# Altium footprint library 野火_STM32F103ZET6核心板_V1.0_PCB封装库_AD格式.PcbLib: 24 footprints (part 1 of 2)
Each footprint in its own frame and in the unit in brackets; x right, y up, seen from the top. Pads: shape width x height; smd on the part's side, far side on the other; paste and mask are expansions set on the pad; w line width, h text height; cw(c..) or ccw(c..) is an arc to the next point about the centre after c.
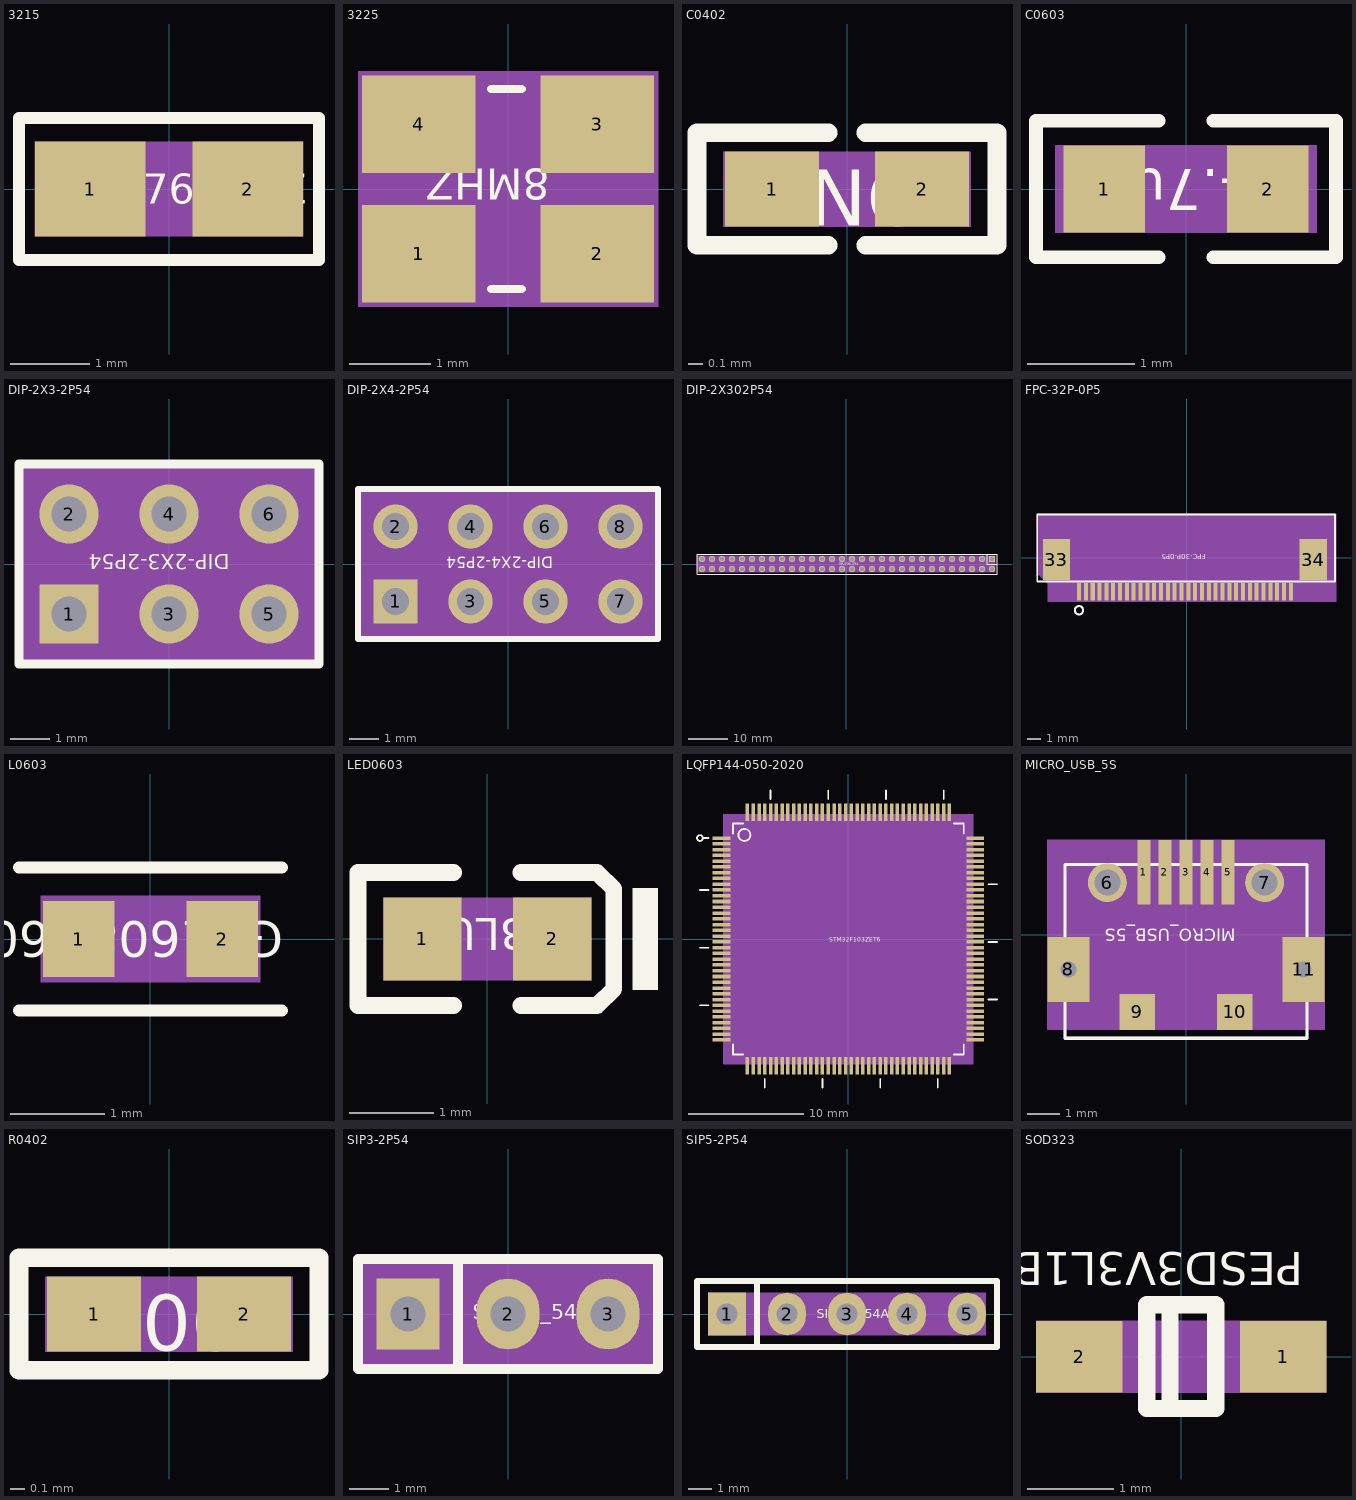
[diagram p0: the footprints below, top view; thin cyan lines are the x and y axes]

## 3215 [mm] "3215"
pads (2):
  rect 1.4x1.2 smd: 1(-1,0) 2(1,0)
Top Overlay:
  lines w0.15: -1.9,-0.9 1.9,-0.9 1.9,0.9 -1.9,0.9 -1.9,-0.9
  text "32.768KHZ" at -1.153,-0.184 h0.38
Mechanical 9:
  text "1" at -1,0.152 h0.38
  text "2" at 1,0.152 h0.38
Mechanical 11:
  region: -1.7,-0.6 1.7,-0.6 1.7,0.6 -1.7,0.6

## 3225 [mil] "3225"
pads (4):
  rect 55.12x47.24 smd: 1(-43.31,-31.49) 2(43.3,-31.49) 3(43.3,31.5) 4(-43.31,31.5)
Top Overlay:
  lines w3.94: -8.31,-48.5 6.69,-48.5 ; -8.31,48.52 6.69,48.52
  text "8MHZ" at 20.15,9.75 h15
Mechanical 9:
  text "1" at -43.31,-37.49 h15
  text "3" at 43.3,25.5 h15
  text "4" at -43.31,25.5 h15
  text "2" at 43.3,-37.49 h15
Mechanical 11:
  region: -72.84,-57.08 72.83,-57.08 72.83,57.09 -72.84,57.09

## C0402 [mil] "C0402"
pads (2):
  rect 25x20 smd: 1(-20,0) 2(20,0)
Top Overlay:
  lines w5: -5,-15 -40,-15 -40,15 -5,15 ; 5,-15 40,-15 40,15 5,15
  text "NC" at -10.05,-9.75 h15
Mechanical 9:
  text "1" at -30,0 h25
  text "2" at 10,0 h25
Mechanical 11:
  region: -33,10 33,10 33,-10 -33,-10

## C0603 [mil] "C0603"
pads (2):
  rect 30x32 smd: 1(-30,0) 2(30,0)
Top Overlay:
  lines w5: -10,-25 -55,-25 -55,25 -10,25 ; 10,-25 55,-25 55,25 10,25
  text "4.7uF" at 25.2,7.25 h15
Mechanical 9:
  text "1" at -20,0 h25
  text "2" at 40,0 h25
Mechanical 11:
  region: -48,16 48,16 48,-16 -48,-16
Mechanical 12:
  text "C0603" at -117,37 h50

## DIP-2X3-2P54 [mil] "DIP-2X3-2P54"
pads (6):
  rect 59.06x59.06 / inner round 60 / far side rect 59.06x59.06 hole 35.43: 1(-100,-50)
  round 59.06 / inner round 60 / far side round 59.06 hole 35.43: 2(-100,50) 3(0,-50) 4(0,50) 5(100,-50) 6(100,50)
Top Overlay:
  lines w8.66: -139.37,100 -150,100 ; -150,100 -150,-100 150,-100 150,100 -150,100
  text "DIP-2X3-2P54" at 60.55,9.75 h15
Mechanical 9:
  text "4" at 0,40 h25
  text "3" at 0,-60 h25
  text "1" at -100,-60 h25
  text "2" at -100,40 h25
  text "5" at 100,-60 h25
  text "6" at 100,40 h25
Mechanical 11:
  region: -150,-100 150,-100 150,100 -150,100
Mechanical 12:
  text ".Designator" at -145,97 h35

## DIP-2X4-2P54 [mil] "DIP-2X4-2P54"
pads (8):
  rect 59.06x59.06 / inner round 60 / far side rect 59.06x59.06 hole 35.43: 1(-150,-50)
  round 59.06 / inner round 60 / far side round 59.06 hole 35.43: 2(-150,50) 3(-50,-50) 4(-50,50) 5(50,-50) 6(50,50) 7(150,-50) 8(150,50)
Top Overlay:
  lines w8.66: -189.37,100 -200,100 ; -200,100 -200,-100 200,-100 200,100 -200,100
  text "DIP-2X4-2P54" at 60.55,9.75 h15
Mechanical 9:
  text "3" at -50,-60 h25
  text "4" at -50,40 h25
  text "5" at 50,-60 h25
  text "6" at 50,40 h25
  text "2" at -150,40 h25
  text "1" at -150,-60 h25
  text "7" at 150,-60 h25
  text "8" at 150,40 h25
Mechanical 11:
  region: -200,-100 200,-100 200,100 -200,100
Mechanical 12:
  text ".Designator" at -195,97 h35

## DIP-2X302P54 [mil] "DIP-2X302P54"
pads (60):
  rect 62.99x62.99 / inner round 60 / far side rect 62.99x62.99 hole 35.43: 1(1459.5,50)
  round 62.99 / inner round 60 / far side round 62.99 hole 35.43: 2(1459.5,-50) 3(1359.5,50) 4(1359.5,-50) 5(1259.5,50) 6(1259.5,-50) 7(1159.5,50) 8(1159.5,-50) 9(1059.5,50) 10(1059.5,-50) 11(959.5,50) 12(959.5,-50) 13(859.5,50) 14(859.5,-50) 15(759.5,50) 16(759.5,-50) 17(659.5,50) 18(659.5,-50) 19(559.5,50) 20(559.5,-50) 21(459.5,50) 22(459.5,-50) 23(359.5,50) 24(359.5,-50) 25(259.5,50) 26(259.5,-50) 27(159.5,50) 28(159.5,-50) 29(59.5,50) 30(59.5,-50) 31(-40.5,50) 32(-40.5,-50) 33(-140.5,50) 34(-140.5,-50) 35(-240.5,50) 36(-240.5,-50) 37(-340.5,50) 38(-340.5,-50) 39(-440.5,50) 40(-440.5,-50) 41(-540.5,50) 42(-540.5,-50) 43(-640.5,50) 44(-640.5,-50) 45(-740.5,50) 46(-740.5,-50) 47(-840.5,50) 48(-840.5,-50) 49(-940.5,50) 50(-940.5,-50) 51(-1040.5,50) 52(-1040.5,-50) 53(-1140.5,50) 54(-1140.5,-50) 55(-1240.5,50) 56(-1240.5,-50) 57(-1340.5,50) 58(-1340.5,-50) 59(-1440.5,50) 60(-1440.5,-50)
Top Overlay:
  lines w12: 1409.5,100 1409.5,0 1509.5,0 ; -1490.5,-100 1509.5,-100 1509.5,100 -1490.5,100 -1490.5,-100
  text "DIP_2X30_2P54" at -65.6,-7.25 h15
Mechanical 9:
  text "60" at -1420.5,-50 h25
  text "7" at 1169.5,50 h25
  text "11" at 979.5,50 h25
  text "33" at -120.5,50 h25
  text "35" at -220.5,50 h25
  text "12" at 979.5,-50 h25
  text "51" at -1020.5,50 h25
  text "45" at -720.5,50 h25
  text "48" at -820.5,-50 h25
  text "40" at -420.5,-50 h25
  text "47" at -820.5,50 h25
  text "36" at -220.5,-50 h25
  text "34" at -120.5,-50 h25
  text "50" at -920.5,-50 h25
  text "49" at -920.5,50 h25
  text "16" at 779.5,-50 h25
  text "21" at 479.5,50 h25
  text "25" at 279.5,50 h25
  text "14" at 879.5,-50 h25
  text "39" at -420.5,50 h25
  text "44" at -620.5,-50 h25
  text "43" at -620.5,50 h25
  text "52" at -1020.5,-50 h25
  text "18" at 679.5,-50 h25
  text "42" at -520.5,-50 h25
  text "41" at -520.5,50 h25
  text "20" at 579.5,-50 h25
  text "56" at -1220.5,-50 h25
  text "55" at -1220.5,50 h25
  text "53" at -1120.5,50 h25
  text "30" at 79.5,-50 h25
  text "27" at 179.5,50 h25
  text "17" at 679.5,50 h25
  text "23" at 379.5,50 h25
  text "15" at 779.5,50 h25
  text "31" at -20.5,50 h25
  text "58" at -1320.5,-50 h25
  text "54" at -1120.5,-50 h25
  text "57" at -1320.5,50 h25
  text "32" at -20.5,-50 h25
  text "29" at 79.5,50 h25
  text "24" at 379.5,-50 h25
  text "22" at 479.5,-50 h25
  text "5" at 1269.5,50 h25
  text "4" at 1369.5,-50 h25
  text "10" at 1079.5,-50 h25
  text "9" at 1069.5,50 h25
  text "8" at 1169.5,-50 h25
  text "13" at 879.5,50 h25
  text "28" at 179.5,-50 h25
  text "26" at 279.5,-50 h25
  text "19" at 579.5,50 h25
  text "1" at 1469.5,50 h25
  text "2" at 1469.5,-50 h25
  text "3" at 1369.5,50 h25
  text "38" at -320.5,-50 h25
  text "37" at -320.5,50 h25
  text "59" at -1420.5,50 h25
  text "6" at 1269.5,-50 h25
  text "46" at -720.5,-50 h25
Mechanical 10:
  region: 1490.5,-81 1490.5,81 -1490.5,81 -1490.5,-81
Mechanical 14:
  text ".Designator" at 1507.5,-115 h35

## FPC-32P-0P5 [mm] "FPC-32P-0P5"
pads (34):
  rect 0.3x1.3 smd: 1(-7.865,-2.483) 2(-7.365,-2.483) 3(-6.865,-2.483) 4(-6.365,-2.483) 5(-5.865,-2.483) 6(-5.365,-2.483) 7(-4.865,-2.483) 8(-4.365,-2.483) 9(-3.865,-2.483) 10(-3.365,-2.483) 11(-2.865,-2.483) 12(-2.365,-2.483) 13(-1.865,-2.483) 14(-1.365,-2.483) 15(-0.865,-2.483) 16(-0.365,-2.483) 17(0.135,-2.483) 18(0.635,-2.483) 19(1.135,-2.483) 20(1.635,-2.483) 21(2.135,-2.483) 22(2.635,-2.483) 23(3.135,-2.483) 24(3.635,-2.483) 25(4.135,-2.483) 26(4.635,-2.483) 27(5.135,-2.483) 28(5.635,-2.483) 29(6.135,-2.483) 30(6.635,-2.483) 31(7.135,-2.483) 32(7.635,-2.483)
  rect 2x3 smd: 33(-9.515,-0.133) 34(9.285,-0.133)
Top Overlay:
  circle w0.152: c-7.865,-3.845 r0.305
  lines w0.127: -10.915,-1.733 10.872,-1.733 10.872,3.167 -10.915,3.167 -10.915,-1.733
  text "FPC-30P-0P5" at 1.41,0.248 h0.38
Mechanical 9:
  text "23" at 3.135,-2.991 h0.64
  text "28" at 5.635,-2.991 h0.64
  text "22" at 2.635,-2.991 h0.64
  text "2" at -7.365,-2.737 h0.64
  text "27" at 5.135,-2.991 h0.64
  text "26" at 4.635,-2.991 h0.64
  text "24" at 3.635,-2.991 h0.64
  text "12" at -2.365,-2.991 h0.64
  text "13" at -1.865,-2.991 h0.64
  text "14" at -1.365,-2.991 h0.64
  text "21" at 2.135,-2.991 h0.64
  text "6" at -5.365,-2.737 h0.64
  text "7" at -4.865,-2.737 h0.64
  text "8" at -4.365,-2.737 h0.64
  text "9" at -3.865,-2.737 h0.64
  text "10" at -3.365,-2.991 h0.64
  text "11" at -2.865,-2.991 h0.64
  text "4" at -6.365,-2.737 h0.64
  text "5" at -5.865,-2.737 h0.64
  text "20" at 1.635,-2.991 h0.64
  text "19" at 1.135,-2.991 h0.64
  text "17" at 0.135,-2.991 h0.64
  text "18" at 0.635,-2.991 h0.64
  text "3" at -6.865,-2.737 h0.64
  text "15" at -0.865,-2.991 h0.64
  text "16" at -0.365,-2.991 h0.64
  text "31" at 7.64,-3.499 h0.64
  text "29" at 6.135,-2.991 h0.64
  text "33" at -9.515,-0.641 h0.64
  text "32" at 8.402,-3.499 h0.64
  text "30" at 6.635,-2.991 h0.64
  text "34" at 9.285,-0.641 h0.64
  text "1" at -7.865,-2.737 h0.64
  text "25" at 4.135,-2.991 h0.64
Mechanical 11:
  region: -10.155,-3.233 10.942,-3.233 10.942,3.232 -10.942,3.232 -10.942,-1.27 -10.79,-1.27 -10.155,-1.905

## L0603 [mil] "L0603"
pads (2):
  rect 30x32 smd: 1(-30,0) 2(30,0)
Top Overlay:
  lines w5: -55,-30 55,-30 ; -55,30 55,30
  text "GZ1608D601TF" at 55.55,7.5 h15
Mechanical 9:
  text "1" at -30,-10 h25
  text "2" at 30,-10 h25
Mechanical 11:
  region: -46,18 46,18 46,-18 -46,-18
Mechanical 12:
  text "L0603" at -115,40 h50
Multi-Layer:
  region: -49,-20 49,-20 49,20 -49,20

## LED0603 [mil] "LED0603"
pads (2):
  rect 36.61x38.58 smd: 1(-30.31,0) 2(30.32,0)
Top Overlay:
  pour cut-out: 67.91,-23.62 79.73,-23.62 79.73,23.62 67.91,23.62
  lines w7.87: -15.75,-31.1 -60.43,-31.1 -60.43,31.1 -15.75,31.1 ; 15.75,-31.1 51.18,-31.1 59.06,-23.5 59.06,23.5 51.18,31.1 15.75,31.1
  text "BLUE" at 20.15,9.75 h15
Mechanical 9:
  text "2" at 40.32,0 h25
  text "1" at -20.31,0 h25
Mechanical 11:
  region: -48.62,-19.29 48.62,-19.29 48.62,19.29 -48.62,19.29

## LQFP144-050-2020 [mil] "LQFP144-050-2020"
pads (144):
  rect 60x12 smd: 1(-433.07,344.49) 2(-433.07,324.8) 3(-433.07,305.12) 4(-433.07,285.43) 5(-433.07,265.75) 6(-433.07,246.06) 7(-433.07,226.38) 8(-433.07,206.69) 9(-433.07,187.01) 10(-433.07,167.32) 11(-433.07,147.64) 12(-433.07,127.95) 13(-433.07,108.27) 14(-433.07,88.58) 15(-433.07,68.9) 16(-433.07,49.21) 17(-433.07,29.53) 18(-433.07,9.84) 19(-433.07,-9.84) 20(-433.07,-29.53) 21(-433.07,-49.21) 22(-433.07,-68.9) 23(-433.07,-88.58) 24(-433.07,-108.27) 25(-433.07,-127.95) 26(-433.07,-147.64) 27(-433.07,-167.32) 28(-433.07,-187.01) 29(-433.07,-206.69) 30(-433.07,-226.38) 31(-433.07,-246.06) 32(-433.07,-265.75) 33(-433.07,-285.43) 34(-433.07,-305.12) 35(-433.07,-324.8) 36(-433.07,-344.49) 73(433.07,-344.49) 74(433.07,-324.8) 75(433.07,-305.12) 76(433.07,-285.43) 77(433.07,-265.75) 78(433.07,-246.06) 79(433.07,-226.38) 80(433.07,-206.69) 81(433.07,-187.01) 82(433.07,-167.32) 83(433.07,-147.64) 84(433.07,-127.95) 85(433.07,-108.27) 86(433.07,-88.58) 87(433.07,-68.9) 88(433.07,-49.21) 89(433.07,-29.53) 90(433.07,-9.84) 91(433.07,9.84) 92(433.07,29.53) 93(433.07,49.21) 94(433.07,68.9) 95(433.07,88.58) 96(433.07,108.27) 97(433.07,127.95) 98(433.07,147.64) 99(433.07,167.32) 100(433.07,187.01) 101(433.07,206.69) 102(433.07,226.38) 103(433.07,246.06) 104(433.07,265.75) 105(433.07,285.43) 106(433.07,305.12) 107(433.07,324.8) 108(433.07,344.49)
  rect 12x60 smd: 37(-344.49,-433.07) 38(-324.8,-433.07) 39(-305.12,-433.07) 40(-285.43,-433.07) 41(-265.75,-433.07) 42(-246.06,-433.07) 43(-226.38,-433.07) 44(-206.69,-433.07) 45(-187.01,-433.07) 46(-167.32,-433.07) 47(-147.64,-433.07) 48(-127.95,-433.07) 49(-108.27,-433.07) 50(-88.58,-433.07) 51(-68.9,-433.07) 52(-49.21,-433.07) 53(-29.53,-433.07) 54(-9.84,-433.07) 55(9.84,-433.07) 56(29.53,-433.07) 57(49.21,-433.07) 58(68.9,-433.07) 59(88.58,-433.07) 60(108.27,-433.07) 61(127.95,-433.07) 62(147.64,-433.07) 63(167.32,-433.07) 64(187.01,-433.07) 65(206.69,-433.07) 66(226.38,-433.07) 67(246.06,-433.07) 68(265.75,-433.07) 69(285.43,-433.07) 70(305.12,-433.07) 71(324.8,-433.07) 72(344.49,-433.07) 109(344.49,433.07) 110(324.8,433.07) 111(305.12,433.07) 112(285.43,433.07) 113(265.75,433.07) 114(246.06,433.07) 115(226.38,433.07) 116(206.69,433.07) 117(187.01,433.07) 118(167.32,433.07) 119(147.64,433.07) 120(127.95,433.07) 121(108.27,433.07) 122(88.58,433.07) 123(68.9,433.07) 124(49.21,433.07) 125(29.53,433.07) 126(9.84,433.07) 127(-9.84,433.07) 128(-29.53,433.07) 129(-49.21,433.07) 130(-68.9,433.07) 131(-88.58,433.07) 132(-108.27,433.07) 133(-127.95,433.07) 134(-147.64,433.07) 135(-167.32,433.07) 136(-187.01,433.07) 137(-206.69,433.07) 138(-226.38,433.07) 139(-246.06,433.07) 140(-265.75,433.07) 141(-285.43,433.07) 142(-305.12,433.07) 143(-324.8,433.07) 144(-344.49,433.07)
Top Overlay:
  circle w6: c-355,355 r20.62
  circle w6: c-506.89,344.49 r9.84
  lines w6: -506.89,-226.38 -477.36,-226.38 ; -506.89,-29.53 -477.36,-29.53 ; -506.89,167.32 -477.36,167.32 ; -497.05,344.49 -477.36,344.49 ; -393.7,-360 -393.7,-393.7 -360,-393.7 ; -393.7,360 -393.7,393.7 -360,393.7 ; -285.43,-506.89 -285.43,-477.36 ; -265.75,477.36 -265.75,506.89 ; -88.58,-506.89 -88.58,-477.36 ; -68.9,477.36 -68.9,506.89 ; 108.27,-506.89 108.27,-477.36 ; 127.95,477.36 127.95,506.89 ; 305.12,-506.89 305.12,-477.36 ; 324.8,477.36 324.8,506.89 ; 360,-393.7 393.7,-393.7 393.7,-360 ; 360,393.7 393.7,393.7 393.7,360 ; 477.36,-206.69 506.89,-206.69 ; 477.36,-9.84 506.89,-9.84 ; 477.36,187.01 506.89,187.01
  text ".Designator" at 26.5,505 h30
  text "STM32F103ZET6" at -65.6,-9.75 h15
Mechanical 9:
  text "71" at 308.8,-433.07 h20
  text "143" at -348.8,433.07 h20
  text "23" at -449.07,-88.58 h20
  text "24" at -449.07,-108.27 h20
  text "8" at -441.07,206.69 h20
  text "9" at -441.07,187.01 h20
  text "106" at 409.07,305.12 h20
  text "6" at -441.07,246.06 h20
  text "124" at 25.21,433.07 h20
  text "93" at 417.07,49.21 h20
  text "92" at 417.07,29.53 h20
  text "91" at 417.07,9.84 h20
  text "90" at 417.07,-9.84 h20
  text "89" at 417.07,-29.53 h20
  text "88" at 417.07,-49.21 h20
  text "87" at 417.07,-68.9 h20
  text "132" at -132.27,433.07 h20
  text "129" at -73.21,433.07 h20
  text "128" at -53.53,433.07 h20
  text "127" at -33.84,433.07 h20
  text "126" at -14.16,433.07 h20
  text "125" at 5.53,433.07 h20
  text "57" at 33.21,-433.07 h20
  text "56" at 13.53,-433.07 h20
  text "21" at -449.07,-49.21 h20
  text "20" at -449.07,-29.53 h20
  text "19" at -449.07,-9.84 h20
  text "18" at -449.07,9.84 h20
  text "15" at -449.07,68.9 h20
  text "14" at -449.07,88.58 h20
  text "13" at -449.07,108.27 h20
  text "12" at -449.07,127.95 h20
  text "55" at -6.16,-433.07 h20
  text "54" at -25.84,-433.07 h20
  text "53" at -45.53,-433.07 h20
  text "50" at -104.58,-433.07 h20
  text "49" at -124.27,-433.07 h20
  text "22" at -449.07,-68.9 h20
  text "11" at -449.07,147.64 h20
  text "10" at -449.07,167.32 h20
  text "60" at 92.27,-433.07 h20
  text "59" at 72.58,-433.07 h20
  text "58" at 52.9,-433.07 h20
  text "5" at -441.07,265.75 h20
  text "4" at -441.07,285.43 h20
  text "3" at -441.07,305.12 h20
  text "2" at -441.07,324.8 h20
  text "1" at -441.07,344.49 h20
  text "68" at 249.75,-433.07 h20
  text "67" at 230.06,-433.07 h20
  text "66" at 210.38,-433.07 h20
  text "65" at 190.69,-433.07 h20
  text "64" at 171.01,-433.07 h20
  text "63" at 151.32,-433.07 h20
  text "142" at -329.12,433.07 h20
  text "141" at -309.43,433.07 h20
  text "78" at 417.07,-246.06 h20
  text "77" at 417.07,-265.75 h20
  text "123" at 44.9,433.07 h20
  text "122" at 64.58,433.07 h20
  text "119" at 123.64,433.07 h20
  text "118" at 143.32,433.07 h20
  text "117" at 163.01,433.07 h20
  text "116" at 182.69,433.07 h20
  text "86" at 417.07,-88.58 h20
  text "85" at 417.07,-108.27 h20
  text "82" at 417.07,-167.32 h20
  text "81" at 417.07,-187.01 h20
  text "80" at 417.07,-206.69 h20
  text "79" at 417.07,-226.38 h20
  text "115" at 202.38,433.07 h20
  text "114" at 222.06,433.07 h20
  text "99" at 417.07,167.32 h20
  text "98" at 417.07,147.64 h20
  text "97" at 417.07,127.95 h20
  text "96" at 417.07,108.27 h20
  text "45" at -203.01,-433.07 h20
  text "44" at -222.69,-433.07 h20
  text "29" at -449.07,-206.69 h20
  text "28" at -449.07,-187.01 h20
  text "7" at -441.07,226.38 h20
  text "113" at 241.75,433.07 h20
  text "112" at 261.43,433.07 h20
  text "111" at 281.12,433.07 h20
  text "27" at -449.07,-167.32 h20
  text "26" at -449.07,-147.64 h20
  text "140" at -289.75,433.07 h20
  text "139" at -270.06,433.07 h20
  text "137" at -230.69,433.07 h20
  text "136" at -211.01,433.07 h20
  text "135" at -191.32,433.07 h20
  text "134" at -171.64,433.07 h20
  text "133" at -151.95,433.07 h20
  text "48" at -143.95,-433.07 h20
  text "76" at 417.07,-285.43 h20
  text "75" at 417.07,-305.12 h20
  text "74" at 417.07,-324.8 h20
  text "73" at 417.07,-344.49 h20
  text "70" at 289.12,-433.07 h20
  text "69" at 269.43,-433.07 h20
  text "47" at -163.64,-433.07 h20
  text "46" at -183.32,-433.07 h20
  text "101" at 409.07,206.69 h20
  text "100" at 409.07,187.01 h20
  text "43" at -242.38,-433.07 h20
  text "42" at -262.06,-433.07 h20
  text "41" at -281.75,-433.07 h20
  text "40" at -301.43,-433.07 h20
  text "37" at -360.49,-433.07 h20
  text "36" at -449.07,-344.49 h20
  text "110" at 300.8,433.07 h20
  text "109" at 320.49,433.07 h20
  text "105" at 409.07,285.43 h20
  text "104" at 409.07,265.75 h20
  text "103" at 409.07,246.06 h20
  text "102" at 409.07,226.38 h20
  text "35" at -449.07,-324.8 h20
  text "34" at -449.07,-305.12 h20
  text "25" at -449.07,-127.95 h20
  text "138" at -250.38,433.07 h20
  text "39" at -321.12,-433.07 h20
  text "17" at -449.07,29.53 h20
  text "52" at -65.21,-433.07 h20
  text "62" at 131.64,-433.07 h20
  text "72" at 328.49,-433.07 h20
  text "84" at 417.07,-127.95 h20
  text "144" at -368.49,433.07 h20
  text "121" at 84.27,433.07 h20
  text "95" at 417.07,88.58 h20
  text "131" at -112.58,433.07 h20
  text "108" at 409.07,344.49 h20
  text "32" at -449.07,-265.75 h20
  text "33" at -449.07,-285.43 h20
  text "38" at -340.8,-433.07 h20
  text "51" at -84.9,-433.07 h20
  text "61" at 111.95,-433.07 h20
  text "30" at -449.07,-226.38 h20
  text "31" at -449.07,-246.06 h20
  text "16" at -449.07,49.21 h20
  text "83" at 417.07,-147.64 h20
  text "120" at 103.95,433.07 h20
  text "130" at -92.9,433.07 h20
  text "94" at 417.07,68.9 h20
  text "107" at 409.07,324.8 h20
Mechanical 11:
  region: -426.31,-426.31 426.31,-426.31 426.31,426.31 -426.31,426.31
Mechanical 12:
  lines w6: -393.7,-360 -393.7,-393.7 -360,-393.7 ; -393.7,360 -393.7,393.7 -360,393.7 ; 360,-393.7 393.7,-393.7 393.7,-360 ; 360,393.7 393.7,393.7 393.7,360
Mechanical 13:
  lines w1: -426.31,-426.31 426.31,-426.31 426.31,426.31 -426.31,426.31 -426.31,-426.31

## MICRO_USB_5S [mm] "MICRO_USB_5S"
pads (11):
  rect 0.4x2 smd: 1(-1.3,1.93) 2(-0.65,1.93) 3(0,1.93) 4(0.65,1.93) 5(1.3,1.93)
  round 1.2 / inner round 1.524 / far side round 1.2 hole 0.8: 6(-2.425,1.61) 7(2.425,1.61)
  rect 1.3x2 / inner round 1.524 / far side rect 1.3x2 hole 0.5: 8(-3.625,-1.07) 11(3.625,-1.07)
  rect 1.1x1.1 smd: 9(-1.5,-2.38) 10(1.5,-2.38)
Top Overlay:
  lines w0.1: -3.73,-3.19 -3.73,2.165 3.73,2.165 3.73,-3.19 -3.73,-3.19
  text "MICRO_USB_5S" at 1.538,0.184 h0.38
Mechanical 9:
  text "5" at 1.3,1.777 h0.38
  text "1" at -1.3,1.777 h0.38
  text "2" at -0.65,1.777 h0.38
  text "3" at 0,1.777 h0.38
  text "7" at 2.425,1.356 h0.64
  text "6" at -2.425,1.356 h0.64
  text "8" at -3.625,-1.223 h0.38
  text "9" at -1.5,-2.533 h0.38
  text "10" at 1.5,-2.685 h0.38
  text "11" at 3.625,-1.375 h0.38
  text "4" at 0.65,1.777 h0.38
Mechanical 11:
  region: -4.275,-2.93 4.275,-2.93 4.275,2.93 -4.275,2.93
Mechanical 12:
  lines w0.1: -3.73,-3.19 -3.73,2.165 3.73,2.165 3.73,-3.19 -3.73,-3.19

## R0402 [mil] "R0402"
pads (2):
  rect 25x20 smd: 1(-20,0) 2(20,0)
Top Overlay:
  lines w5: -40,-15 -40,15 40,15 40,-15 -40,-15
  text "100R" at -20.15,-9.75 h15
Mechanical 9:
  text "2" at 15.2,-5 h12
  text "1" at -24.8,-5 h12
Mechanical 11:
  region: -33,10 33,10 33,-10 -33,-10
Mechanical 12:
  text "R0402" at -115,36 h50

## SIP3-2P54 [mil] "SIP3-2P54"
pads (3):
  rect 62.99x70.87 / inner round 60 / far side rect 62.99x70.87 hole 35.43: 1(-100,0)
  oval 62.99x70.87 / inner round 60 / far side oval 62.99x70.87 hole 35.43: 2(0,0) 3(100,0)
Top Overlay:
  lines w10: -50,-55.12 -50,55.12 ; -150,-55.12 -150,55.12 150,55.12 150,-55.12 -150,-55.12
  text "SIP3_2_54" at -35.4,-5 h15
Mechanical 9:
  text "1" at -100,6 h15
  text "3" at 100,6 h15
  text "2" at 0,6 h15
Mechanical 11:
  region: -150,-50 150,-50 150,50 -150,50

## SIP5-2P54 [mil] "SIP5-2P54"
pads (5):
  rect 62.99x70.87 / inner round 60 / far side rect 62.99x70.87 hole 35.43: 1(-200,0)
  oval 62.99x70.87 / inner round 60 / far side oval 62.99x70.87 hole 35.43: 2(-100,0) 3(0,0) 4(100,0) 5(200,0)
Top Overlay:
  lines w10: -150,-55.12 -150,55.12 ; -250,-55.12 -250,55.12 250,55.12 250,-55.12 -250,-55.12
  text "SIP5_2_54A" at -50.45,-7.25 h15
Mechanical 9:
  text "2" at -100,6 h15
  text "4" at 100,6 h15
  text "1" at -200,6 h15
  text "5" at 200,6 h15
  text "3" at 0,6 h15
Mechanical 11:
  region: -231.5,-35.43 231.5,-35.43 231.5,35.43 -231.5,35.43

## SOD323 [mm] "SOD323"
pads (2):
  rect 1x0.83 smd: 1(1.18,0) 2(-1.18,0)
Top Overlay:
  lines w0.2: -0.13,-0.6 -0.13,0.6 ; -0.4,-0.6 0.4,-0.6 0.4,0.6 -0.4,0.6 -0.4,-0.6
  text "PESD3V3L1BA" at 1.41,1.206 h0.38
Mechanical 9:
  text "2" at -0.926,0 h0.64
  text "1" at 1.434,0 h0.64
Mechanical 11:
  region: -1.68,-0.415 1.68,-0.415 1.68,0.415 -1.68,0.415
